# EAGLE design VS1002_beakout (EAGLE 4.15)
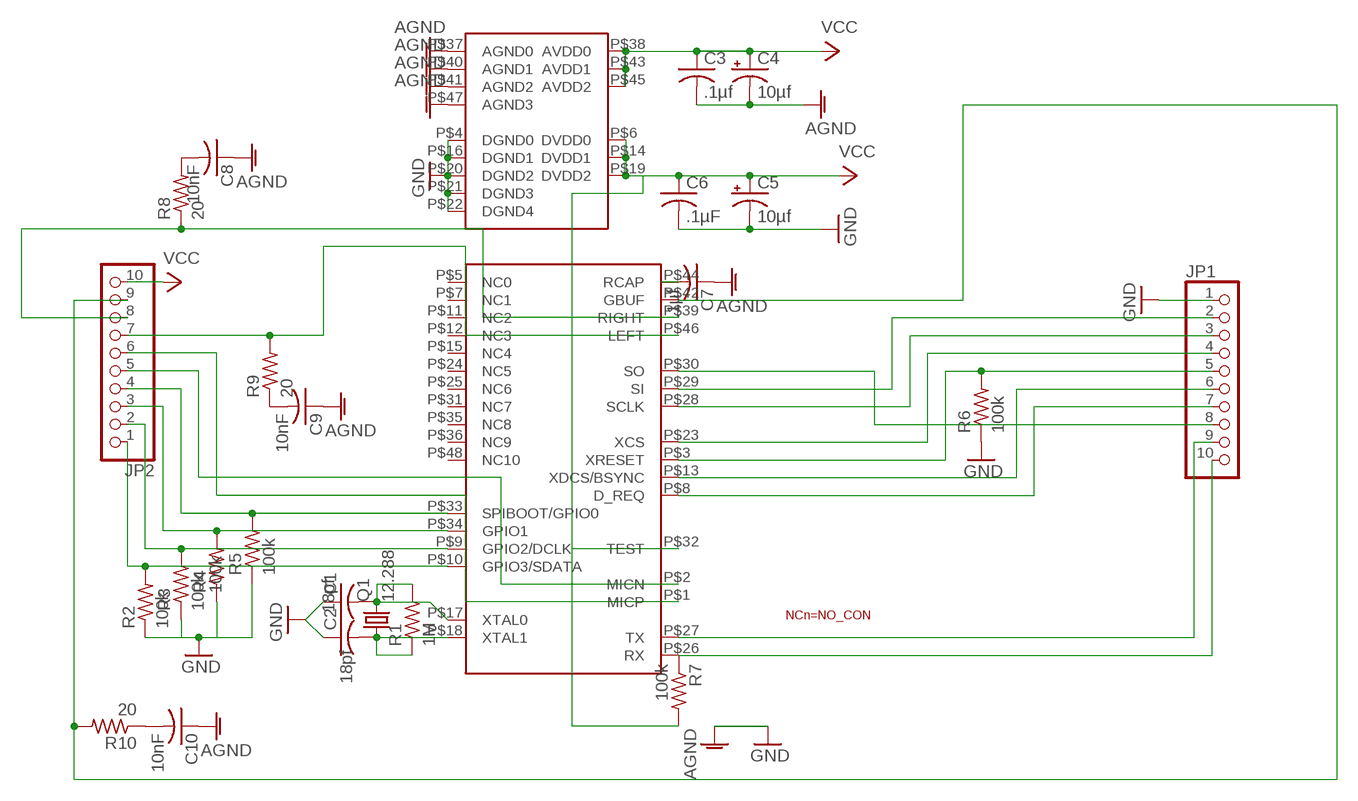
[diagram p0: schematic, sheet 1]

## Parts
C1  18pf  C-USC0402  [C0402]
C2  18pf  C-USC0402  [C0402]
C3  .1µf  C-USC0402  [C0402]
C4  10µf  CPOL-USCT3216  [CT3216]
C5  10µf  CPOL-USCT3216  [CT3216]
C6  .1µF  C-USC0402  [C0402]
C7  .1µf  C-USC0402  [C0402]
C8  10nF  C-USC0402  [C0402]
C9  10nF  C-USC0402  [C0402]
C10  10nF  C-USC0402  [C0402]
JP1  PINHD-1X10  [1X10]
JP2  PINHD-1X10  [1X10]
Q1  12.288  CRYTALHC49UP  [HC49UP]
R1  1M  R-US_R0402  [R0402]
R2  100k  R-US_R0402  [R0402]
R3  100k  R-US_R0402  [R0402]
R4  100k  R-US_R0402  [R0402]
R5  100k  R-US_R0402  [R0402]
R6  100k  R-US_R0402  [R0402]
R7  100k  R-US_R0402  [R0402]
R8  20  R-US_R0402  [R0402]
R9  20  R-US_R0402  [R0402]
R10  20  R-US_R0402  [R0402]
U$1  VS1002  [LQFP-48]

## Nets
AGND: C3.2 C4.- C7.1 C8.1 C9.1 C10.1 U$1.P$37(AGND0) U$1.P$40(AGND1) U$1.P$41(AGND2) U$1.P$47(AGND3)
GND: C1.1 C2.1 C5.- C6.2 JP1.1 R2.1 R3.1 R4.1 R5.1 R6.1 U$1.P$4(DGND0) U$1.P$16(DGND1) U$1.P$20(DGND2) U$1.P$21(DGND3) U$1.P$22(DGND4) ; supply symbol labelled AGND
N$1: C2.2 Q1.1 R1.1 U$1.P$18(XTAL1)
N$2: C1.2 Q1.2 R1.2 U$1.P$17(XTAL0)
N$3: JP2.1 R2.2 U$1.P$10(GPIO3/SDATA)
N$4: JP2.2 R3.2 U$1.P$9(GPIO2/DCLK)
N$5: JP2.3 R4.2 U$1.P$34(GPIO1)
N$6: JP2.4 R5.2 U$1.P$33(SPIBOOT/GPIO0)
N$7: JP1.8 U$1.P$30(SO)
N$8: JP1.2 U$1.P$29(SI)
N$9: JP1.3 U$1.P$28(SCLK)
N$10: JP1.4 U$1.P$23(XCS)
N$11: JP1.5 R6.2 U$1.P$3(XRESET)
N$12: JP1.6 U$1.P$13(XDCS/BSYNC)
N$13: JP1.7 U$1.P$8(D_REQ)
N$14: JP2.7 R9.2 U$1.P$46(LEFT)
N$15: JP2.8 R8.1 U$1.P$39(RIGHT)
N$16: JP2.9 R10.2 U$1.P$42(GBUF)
N$17: C8.2 R8.2
N$18: C9.2 R9.1
N$19: C10.2 R10.1
N$20: JP1.10 R7.1 U$1.P$26(RX)
N$21: C7.2 U$1.P$44(RCAP)
N$22: JP1.9 U$1.P$27(TX)
N$23: JP2.5 U$1.P$2(MICN)
N$24: JP2.6 U$1.P$1(MICP)
VCC: C3.1 C4.+ C5.+ C6.1 JP2.10 R7.2 U$1.P$6(DVDD0) U$1.P$14(DVDD1) U$1.P$19(DVDD2) U$1.P$32(TEST) U$1.P$38(AVDD0) U$1.P$43(AVDD1) U$1.P$45(AVDD2)
Unconnected: U$1.P$5(NC0) U$1.P$7(NC1) U$1.P$11(NC2) U$1.P$12(NC3) U$1.P$15(NC4) U$1.P$24(NC5) U$1.P$25(NC6) U$1.P$31(NC7) U$1.P$35(NC8) U$1.P$36(NC9) U$1.P$48(NC10)

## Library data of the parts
C1-C3 C6-C10 = rcl:C-US: CAPACITOR, American symbol
C4 C5 = rcl:CPOL-US: POLARIZED CAPACITOR, American symbol
JP1 JP2 = pinhead:PINHD-1X10: PIN HEADER
Q1 = crystal:CRYTAL: CRYSTAL
R1-R10 = rcl:R-US_: RESISTOR, American symbol
U$1 = VS10XX:VS1002

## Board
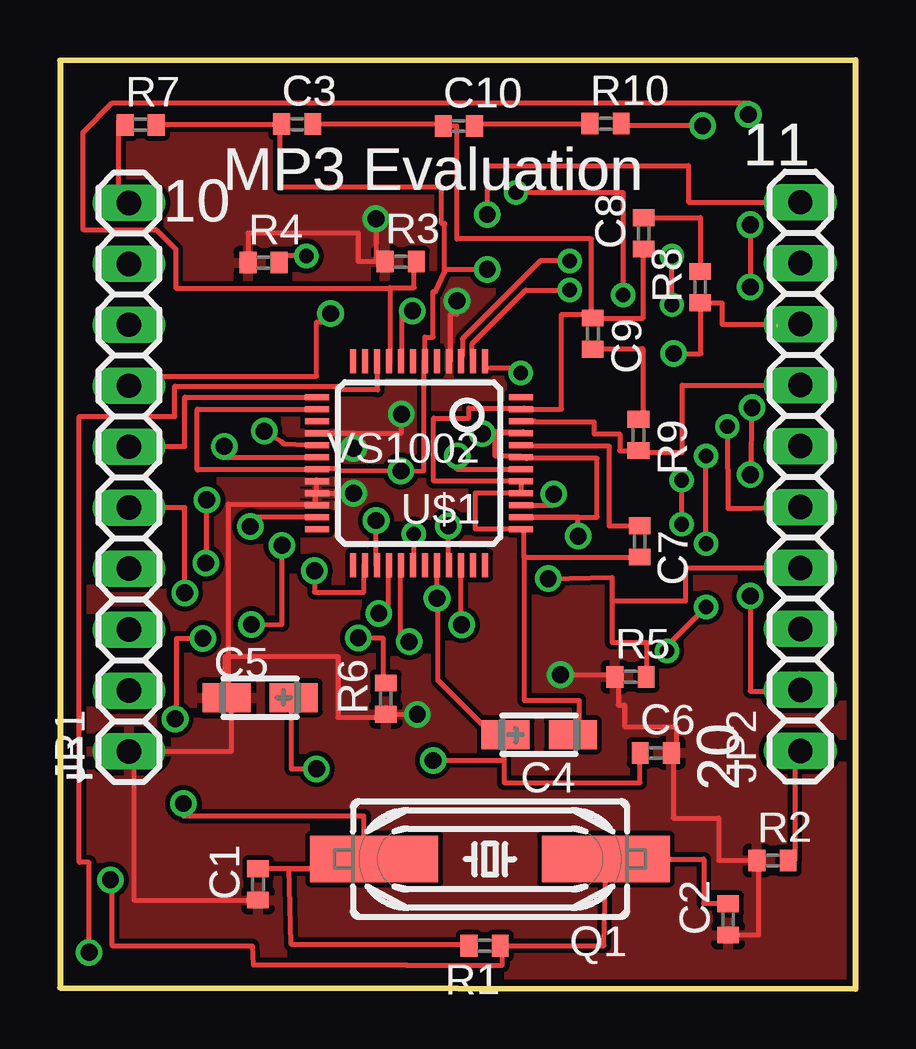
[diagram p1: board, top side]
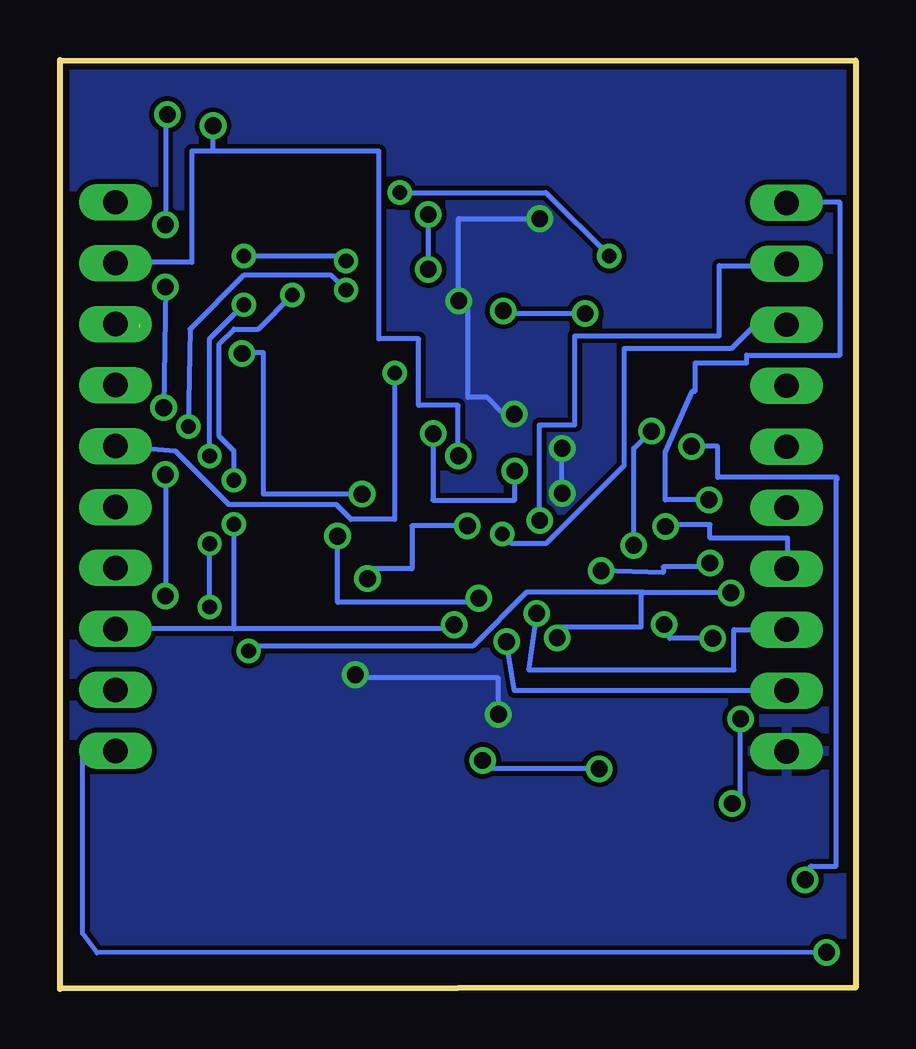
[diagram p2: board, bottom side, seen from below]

Size 33.17 x 38.7 mm. Coordinates in mm from the lower left corner, seen from the top.
Outline: 0,0.05 33.17,0 33.17,38.7 0,38.67 0,0.05
Copper layers (1*16): Top 0.035mm / dielectric 1.5mm / Bottom 0.035mm
Design rules "8mils": minimum track width 8mil, minimum drill 24mil, track to track 8mil, track to pad 8mil, pad to pad 8mil, via to via 8mil, smd to smd 8mil, copper to edge 10mil, drill to drill 10mil, minimum pad ring 10mil, minimum via ring 8mil, stop-mask expansion 0mil, vias tented up to drill 0mil, thermal gap 10mil

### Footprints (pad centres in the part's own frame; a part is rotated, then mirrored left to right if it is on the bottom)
C0402 = smd 0.7 x 0.9: 1 -0.65,0; 2 0.65,0
CT3216 = smd 2 x 1.2: + 1.4,0; - -1.4,0
1X10 = drill 1.016 long: 1 -11.43,0; 2 -8.89,0; 3 -6.35,0; 4 -3.81,0; 5 -1.27,0; 6 1.27,0; 7 3.81,0; 8 6.35,0; 9 8.89,0; 10 11.43,0
HC49UP = smd 5.334 x 1.93: 1 -4.826,0; 2 4.826,0
R0402 = smd 0.7 x 0.9: 1 -0.65,0; 2 0.65,0
LQFP-48 = smd 0.25 x 1: P$1 -2.75,-4.25; P$2 -2.25,-4.25; P$3 -1.75,-4.25; P$4 -1.25,-4.25; P$5 -0.75,-4.25; P$6 -0.25,-4.25; P$7 0.25,-4.25; P$8 0.75,-4.25; P$9 1.25,-4.25; P$10 1.75,-4.25; P$11 2.25,-4.25; P$12 2.75,-4.25; P$25 2.75,4.25; P$26 2.25,4.25; P$27 1.75,4.25; P$28 1.25,4.25; P$29 0.75,4.25; P$30 0.25,4.25; P$31 -0.25,4.25; P$32 -0.75,4.25; P$33 -1.25,4.25; P$34 -1.75,4.25; P$35 -2.25,4.25; P$36 -2.75,4.25 | smd 1 x 0.25: P$13 4.25,-2.75; P$14 4.25,-2.25; P$15 4.25,-1.75; P$16 4.25,-1.25; P$17 4.25,-0.75; P$18 4.25,-0.25; P$19 4.25,0.25; P$20 4.25,0.75; P$21 4.25,1.25; P$22 4.25,1.75; P$23 4.25,2.25; P$24 4.25,2.75; P$37 -4.25,2.75; P$38 -4.25,2.25; P$39 -4.25,1.75; P$40 -4.25,1.25; P$41 -4.25,0.75; P$42 -4.25,0.25; P$43 -4.25,-0.25; P$44 -4.25,-0.75; P$45 -4.25,-1.25; P$46 -4.25,-1.75; P$47 -4.25,-2.25; P$48 -4.25,-2.75

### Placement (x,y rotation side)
C1  8.26,4.35 90 top
C2  27.86,2.89 90 top
C3  9.9,36.03 0 top
C4  19.98,10.59 180 top
C5  8.35,12.13 0 top
C6  24.84,9.83 0 top
C7  24.16,18.64 90 top
C8  24.34,31.48 90 top
C9  22.22,27.3 270 top
C10  16.63,35.95 0 top
JP1  2.88,21.32 90 top
JP2  30.87,21.34 90 top
Q1  17.93,5.41 180 top
R1  17.7,1.79 180 top
R2  29.71,5.35 0 top
R3  14.21,30.3 0 top
R4  8.49,30.26 0 top
R5  23.79,13 0 top
R6  13.59,12.09 90 top
R7  3.37,36 0 top
R8  26.69,29.24 90 top
R9  24.12,23.08 270 top
R10  22.75,36.05 0 top
U$1  14.98,21.91 180 top

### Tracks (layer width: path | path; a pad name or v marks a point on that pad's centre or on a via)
AGND
  Top 0.203: C7.1 19.34,17.99 19.34,18.04 | 19.34,18.04 19.34,19.16 U$1.P$37 17.32,19.16 17.32,20.66 19.39,20.66 | 15.91,35.95 15.91,35.94 | C10.1 15.91,35.95 | 15.91,35.95 15.91,36.03 | C10.1 15.98,36.03 C3.2 | C10.1 16.55,35.95 16.55,31.25 22.16,31.25 22.16,27.95 C9.1 | C8.1 24.32,30.83 24.32,27.95 C9.1 | 19.39,20.66 U$1.P$40 19.25,20.66 19.25,21.16 | 19.39,20.66 19.39,20.68 | 19.25,21.16 19.25,21.17 | 19.25,21.16 U$1.P$41 15.58,21.16 15.58,23.78 17.04,23.78 17.04,24.19 19.36,24.19 19.36,24.16 | 19.36,24.16 19.36,24.15 | 19.36,24.16 U$1.P$47 20.91,24.16 20.91,28.1 22.29,28.1 22.29,27.95 C9.1 | C4.- 21.64,10.59 21.64,12.02 19.36,12.02 19.36,18.04 19.34,18.04
GND  (via drill 0.7 pad 0.25)
  Top 0.203: 3.08,9.89 JP1.1 | C1.1 3.08,3.7 3.08,9.89 | 7.15,12.13 7.15,12.2 | 7.15,12.13 C5.- | 3.08,9.89 7.15,9.89 7.15,12.13 | C2.1 29.12,2.24 29.12,5.35 R2.1 27.47,5.35 27.47,7.12 25.56,7.12 25.56,9.83 | 25.56,9.83 25.56,10.04 | 25.56,9.83 C6.2 25.69,9.83 25.69,10.93 23.53,10.93 23.53,11.81 23.28,11.81 23.28,13 R5.1 23.15,13 23.15,13.08 v20.86,13.08 | C5.- 6.89,12.13 6.89,13.85 11.59,13.85 11.59,11.31 13.63,11.31 13.63,11.44 R6.1 14.51,11.44 v14.9,11.43 | C5.- 7.02,12.13 7.02,20.2 10.32,20.2 10.32,20.16 U$1.P$22 10.65,20.16 10.65,20.66 U$1.P$21 | 7.84,30.22 7.84,30.13 | 7.84,30.22 R4.1 | 7.84,30.22 7.84,31.48 12.44,31.48 12.44,30.3 R3.1 13.17,30.3 v13.17,32.09 | v16.55,28.67 16.55,28.1 16.27,28.1 16.27,26.16 | 16.27,26.16 16.27,26.14 | 16.27,26.16 U$1.P$4 | U$1.P$21 10.69,20.66 10.69,21.16 | 10.69,21.16 U$1.P$20 | 10.69,21.16 10.69,21.22 | v14.23,23.95 14.23,23.16 U$1.P$16 12.24,23.16 v12.24,22.52 | U$1.P$21 10.61,20.66 10.61,20.65 v12.24,20.65
  Bottom 0.203: v14.9,11.43 14.9,12.96 20.86,12.96 v20.86,13.08 | v13.17,32.09 16.55,32.09 v16.55,28.67 16.17,28.3 16.17,24.64 15.35,24.64 14.74,24.03 v14.23,23.95 | v12.24,20.65 v12.24,22.52
  pour Bottom: -0.74,39.38 34.64,39.38 34.64,-1.03 -0.97,-1.03 -0.97,39.38
  pour Top: -1.37,39.63 34.97,39.63 34.97,-1.26 -1.37,-1.26 -1.37,39.53
N$1  (via drill 0.7)
  Top 0.203: 22.77,5.41 Q1.1 22.73,5.41 22.73,5.83 22.57,5.83 22.57,5.67 | 22.77,5.41 22.69,1.79 R1.1 18.45,1.79 18.45,0.98 14.4,0.98 14.45,1 8.06,1 8.01,1.79 2.19,1.79 2.19,4.54 v2.11,4.54 | 22.77,5.41 26.83,5.41 26.83,3.56 27.85,3.56 C2.2 | U$1.P$18 6.85,22.16 v6.85,22.6
  Bottom 0.203: v6.85,22.6 5.76,22.6 5.76,21.3 0.78,21.3 0.78,21.22 0.81,21.22 0.81,5.11 1.86,5.11 v2.11,4.54
N$2  (via drill 0.7 pad 0.25)
  Top 0.203: 12.99,5.41 12.99,5.46 12.67,5.46 12.67,7.2 5.15,7.2 v5.15,7.72 | 12.99,5.41 Q1.2 | 12.99,5 C1.2 | 12.99,5 12.99,5.41 | 12.99,5 9.56,5 9.64,1.85 17.26,1.85 17.18,1.47 R1.2 | v4.8,11.25 4.86,11.25 4.86,14.6 v5.96,14.6 | v7.98,15.18 9.26,15.18 v9.26,18.48 | v8.51,23.24 9.19,22.83 9.31,22.72 10.82,22.64 10.82,22.66 U$1.P$17
  Bottom 0.203: v5.15,7.72 4.8,7.72 v4.8,11.25 | v5.96,14.6 7.75,14.6 v7.98,15.18 | v9.26,18.48 9.26,22.52 v8.51,23.24
N$3  (via drill 0.7)
  Top 0.203: 30.39,5.35 R2.2 30.63,5.35 30.63,9.91 JP2.1 | U$1.P$10 13.24,26.16 13.24,24.99 | 13.24,24.99 13.24,24.95 | 13.24,24.99 11.71,24.99 11.71,25.11 4.78,25.11 4.78,23.86 0.81,23.86 0.81,5.27 1.22,5.27 v1.22,1.52 1.22,2.36
  Bottom 0.203: v1.22,1.52 31.63,1.5 32.23,2.31 32.23,9.84 31.16,9.86 | 31.16,9.86 31.16,9.91 JP2.1 | 31.16,9.86 31.16,9.76
N$4  (via drill 0.7)
  Top 0.203: R3.2 14.77,30.3 14.77,29.21 13.75,29.21 13.75,29.19 | 13.75,26.16 13.75,26.04 | 13.75,26.16 U$1.P$9 | 13.75,29.19 13.75,26.16 | 13.75,29.19 4.82,29.19 4.82,30.82 4.01,31.63 0.96,31.63 0.96,35.7 2.18,36.91 28.7,36.91 v28.7,36.43 | 13.75,29.19 13.76,29.19 | 30.83,13.14 JP2.2 30.76,12.45 | v28.78,31.83 v28.78,29.24 | v28.85,24.21 v28.78,21.42 | v28.78,16.37 28.78,12.4 30.76,12.4 30.76,12.45 | 30.76,12.45 30.76,12.48
  Bottom 0.203: v28.7,36.43 28.78,36.43 v28.78,31.83 | v28.78,29.24 v28.85,24.21 | v28.78,21.42 v28.78,16.37
N$5  (via drill 0.61, 0.7)
  Top 0.203: U$1.P$34 16.72,15.61 v16.74,15.17 | v10.27,30.53 9.46,30.53 R4.2 | v19.01,33.18 23.48,33.18 v23.48,28.91 | v25.92,19.36 v25.92,21.19
  Bottom 0.203: 25.92,14.99 17.05,14.99 v16.74,15.17 | 25.92,14.99 JP2.3 | v10.27,30.53 12.91,33.18 v19.01,33.18 | v23.48,28.91 24.9,27.49 25.92,27.49 26.53,26.88 26.53,23.02 25.92,22.41 v25.92,21.19 | 25.92,14.99 v25.92,19.36
N$6  (via drill 0.7 pad 0.25)
  Top 0.203: U$1.P$33 16.19,17.66 v16.19,19.29 | v20.35,17.09 23.01,17.15 23.01,15.64 | 23.01,15.64 23.01,14.43 24.46,14.43 24.46,13 | 24.46,13 24.46,12.87 | 24.46,13 R5.2 | JP2.4 26.09,17.53 26.09,16.16 23.02,16.16 23.02,15.64 23.01,15.64
  Bottom 0.203: v16.19,19.29 18.5,19.29 18.5,17.49 20.35,17.49 v20.35,17.09
N$7  (via drill 0.61)
  Top 0.203: v14.74,18.95 14.74,18.14 U$1.P$30
  Bottom 0.203: v14.74,18.95 14.34,18.55 12.91,18.55 9.66,21.8 9.66,26.67 5.19,26.67 4.38,27.49 JP1.8
N$8  (via drill 0.7 pad 0.25)
  Top 0.203: 14.19,17.66 14.19,17.88 | 14.19,17.66 U$1.P$29 | v14.56,14.46 14.19,14.46 14.19,17.66
  Bottom 0.203: JP1.2 14.23,12.43 v14.56,14.46
N$9  (via drill 0.7 pad 0.25)
  Top 0.203: 13.7,17.66 13.7,17.68 | 13.7,17.66 U$1.P$28 | v13.3,15.64 13.7,15.64 13.7,17.66
  Bottom 0.203: JP1.3 5.08,14.97 5.08,13.28 13.62,13.28 v13.3,15.64
N$10  (via drill 0.7)
  Top 0.203: v7.93,19.26 8.17,18.94 8.17,19.67 10.64,19.67 10.6,19.66 U$1.P$23
  Bottom 0.203: JP1.4 2.83,17.51 2.83,18.78 6.07,18.78 6.07,19.34 7.69,19.34 v7.93,19.26
N$11  (via drill 0.61, 0.7 pad 0.25)
  Top 0.203: JP1.5 5.2,20.05 v5.2,16.5 | 13.46,12.74 13.46,12.71 | 13.46,12.74 R6.2 | v12.44,14.62 13.46,14.62 13.46,12.74 | v21.25,30.33 20.03,30.33 16.77,27.08 16.77,26.47 U$1.P$3 | v25.51,28.5 v25.51,30.53 | v26.93,18.55 v26.93,22.2 | v26.93,15.9 25.31,14.28 v25.31,14.08
  Bottom 0.203: v5.2,16.5 8.85,16.5 | 8.85,16.5 8.95,16.5 8.95,15.07 12.44,15.07 v12.44,14.62 | v21.25,30.33 21.45,30.53 v25.51,30.53 | v25.51,28.5 26.93,27.08 v26.93,22.2 | v26.93,15.9 v26.93,18.55 | v25.31,14.08 25.11,14.28 15.96,14.28 13.73,16.51 8.85,16.51 8.85,16.5
N$12
  Top 0.203: U$1.P$13 5.2,24.66 5.2,22.6 2.92,22.6 2.92,22.59 | 2.92,22.59 2.92,22.56 | JP1.6 2.92,22.59
N$13  (via drill 0.7 pad 0.25)
  Top 0.203: JP1.7 3.99,25.13 3.99,25.53 10.7,25.53 10.7,27.79 11.28,27.79 v11.28,28.13 | U$1.P$8 14.23,28.25 v14.69,28.25
  Bottom 0.203: v11.28,28.13 14.46,28.13 v14.69,28.25
N$14
  Top 0.203: 19.47,23.66 19.79,23.66 | U$1.P$46 19.47,23.66 | 19.47,23.66 19.5,23.62 22.26,23.62 22.26,23.12 23.34,23.12 23.34,22.43 R9.2 24.17,22.43 | JP2.7 25.94,25.15 25.94,22.36 24.17,22.36 24.17,22.43 | 24.17,22.43 24.17,22.48
N$15  (via drill 0.7, 0.7 pad 0.25)  (1 unrouted)
  Top 0.203: JP2.8 29.88,27.69 27.6,27.69 27.6,28.58 26.71,28.58 26.71,28.59 R8.1 26.72,28.59 | U$1.P$39 20.58,20.16 v20.58,20.61 | 26.72,28.59 26.72,28.63 | v25.58,26.47 26.72,26.47 26.72,28.59
  Bottom 0.203: v20.58,20.61 24.69,20.61 24.69,26.51 25.58,26.51 v25.58,26.47
N$16  (via drill 0.7 pad 0.25)
  Top 0.203: U$1.P$42 16.54,21.66 16.54,22.27 16.54,22.26 v16.56,22.21 | 23.37,35.96 23.37,36.05 R10.2 | v26.79,35.96 23.37,35.96 | 23.37,35.96 23.37,35.88
  Bottom 0.203: v16.56,22.21 16.57,22.47 16.57,24.31 18.22,24.31 18.22,27.08 19.87,27.08 19.87,34.9 26.79,34.9 | 26.79,34.9 v26.79,35.96 | 26.79,34.9 27.68,34.9 27.68,30.27 29.88,30.27 29.88,30.23 | 29.88,30.23 29.88,30.19 | 29.88,30.23 JP2.9
N$17
  Top 0.203: 26.71,29.89 26.71,29.85 | 26.71,29.89 R8.2 | C8.2 26.71,32.13 26.71,29.89
N$18
  Top 0.203: R9.1 24.29,23.73 24.29,26.67 22.26,26.67 22.26,26.65 | 22.26,26.65 22.26,26.55 | C9.2 22.26,26.65
N$19
  Top 0.203: 17.44,35.95 17.44,35.94 | C10.2 17.44,35.95 | R10.1 17.44,36.05 17.44,35.95
N$20  (via drill 0.7)
  Top 0.203: 2.45,36 2.45,36.2 | 2.45,36 R7.1 | JP1.10 2.45,32.75 2.45,36 | U$1.P$26 12.68,17.66 12.68,16.53 10.61,16.53 v10.61,17.42 | v6.08,17.74 6.12,17.7 v6.12,20.37 6.12,20.66
  Bottom 0.203: v10.61,17.42 8.02,17.34 8.02,17.58 6.28,17.58 v6.08,17.74 | v6.12,20.37 7.94,20.37 7.94,22.36 6.81,24.91 6.69,24.91 6.69,26.08 4.54,26.08 4.54,26.41 0.65,26.41 0.65,32.77 2.75,32.77 2.75,32.75 | 2.75,32.75 2.75,32.61 | 2.75,32.75 JP1.10
N$21
  Top 0.203: C7.2 22.9,19.29 22.9,22.61 19.21,22.61 U$1.P$44
N$22  (via drill 0.7 pad 0.25)
  Top 0.203: U$1.P$27 13.18,17.66 v13.18,19.51
  Bottom 0.203: v13.18,19.51 13.19,19.51 13.19,23.5 11.71,23.5 11.71,27.2 5.69,27.2 5.69,30.13 2.68,30.13 2.68,30.21 JP1.9
N$23  (via drill 0.61)
  Top 0.203: v21.25,29.11 19.42,29.11 17.18,26.88 17.18,26.47 U$1.P$2 | v27.82,23.42 27.82,23.3 27.85,20.02 28.84,20.02 JP2.5
  Bottom 0.203: v21.25,29.11 21.85,29.72 25.51,29.72 27.75,27.49 v27.82,23.42
N$24  (via drill 0.61)
  Top 0.203: v19.21,25.66 19.21,25.86 17.79,25.86 U$1.P$1
  Bottom 0.203: v19.21,25.66 19.21,19.56 21.04,19.56 21.65,20.17 26.12,20.17 28.36,22.41 JP2.6
VCC  (via drill 0.7 pad 0.25)
  Top 0.203: 9.05,36.03 9.05,36.2 | 9.05,36.03 C3.1 9.18,36.03 9.18,33.4 15.91,33.4 15.91,31.88 16.04,31.88 16.04,29.85 | R7.2 9.05,36 9.05,36.03 | 16.04,29.85 15.66,29.05 15.56,29.05 | JP2.10 26.2,32.77 26.2,34.29 17.82,34.29 v17.82,32.26 | v17.82,29.98 16.04,29.98 16.04,29.85 | v21.6,18.86 21.6,19.66 U$1.P$38 22.39,19.66 22.39,22.1 19.47,22.1 19.47,22.16 U$1.P$43 19.2,22.16 19.2,22.19 18.14,22.19 18.14,23.21 19.32,23.21 19.32,23.16 U$1.P$45 17.61,23.16 v17.61,23.13 | U$1.P$32 15.72,17.52 v15.72,16.27 15.76,15.9 15.76,12.86 17.59,11.03 C4.+ | U$1.P$14 5.73,24.16 5.73,21.63 10.9,21.63 10.9,21.66 U$1.P$19 10.61,21.66 10.61,21.67 11.63,21.67 11.63,21.58 v14.21,21.57 15.17,21.58 15.17,26.16 U$1.P$6 15.21,26.17 15.21,27.15 15.56,27.15 15.56,29.05 | C5.+ 9.66,12.13 9.66,9.17 v10.7,9.17 | 18.5,10.59 18.5,10.67 | 18.5,10.59 C4.+ | v15.55,9.51 18.5,9.51 18.5,10.59 | C4.+ 18.51,10.59 18.51,8.59 24.18,8.59 C6.1 | C6.1 24.18,9.92 | C6.1 | 15.56,29.05 15.56,29.06
  Bottom 0.203: v17.82,29.98 v17.82,32.26 | v21.6,18.86 21.6,16.1 15.74,16.1 v15.72,16.27 | v17.61,23.13 v17.62,23.13 17.62,20.36 14.21,20.36 v14.21,21.57 | v10.7,9.17 15.55,9.17 v15.55,9.51

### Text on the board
tNames: 11 | MP3 Evaluation | 10 | 1 | 20
_tsilk: R7 | C3 | C10 | R10 | 11 | MP3 Evaluation | 10 | R3 | R4 | C8 | R8 | C9 | VS1002 | R9 | U$1 | C7 | R5 | C5 | R6 | C6 | C4 | 1 | 20 | R2 | C1 | Q1 | C2 | R1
